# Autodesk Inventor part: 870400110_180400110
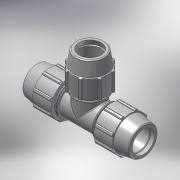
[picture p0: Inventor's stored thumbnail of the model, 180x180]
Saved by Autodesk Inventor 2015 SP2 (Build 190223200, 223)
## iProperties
Created: 2017-02
Part Number: 870400110_180400110
Material: PVC-Piping
Description: PLASSON TEE 110-110-110
Document SubType Name: Modeling
Designer: KIM
Mass: 92.6774 g
Surface Area: 199.44 cm^2
Volume: 66.1981 cm^3
Density: 1.4 g/cm^3
Appearance: Smooth - White
Author: KIM
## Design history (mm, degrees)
derived "87040.ipt"
feature "Solid1::87040.ipt"
tag "TaggingFeature1"
body "Solid1"
other parameters: "d4" = 24.5, "d5" = 73.5, "d7" = 181, "d13" = 120 deg, "d14" = 143, "d15" = 8 deg, "d18" = 5.5, "d19" = 35 deg, "d20" = 17.5 deg, "d21" = 168.33, "d23" = 0, "d25" = 360 deg, "d27" = 3.62, "d42" = 102.9, "d43" = 5.43, "d46" = 3.3, "d63" = 196, "d67" = 135.75, "d77" = 181, "d78" = 8 deg, "d79" = 294, "d80" = 120 deg, "d81" = 143, "d82" = 24.5, "d85" = 135.75, "d87" = 9.8, "d88" = 9.8, "d89" = 73.5, "d90" = 102.9, "d98" = 168.33, "d99" = 35 deg, "d100" = 17.5 deg, "d102" = 0, "d103" = 3.62, "d107" = 360 deg, "d109" = 3.3, "d112" = 5.5, "d118" = 360 deg, "d121" = 0, "d128" = 583, "d131" = 99, "d132" = 99, "d133" = 196, "d134" = 3.92, "d152" = 0, "d154" = 0, "d156" = 0, "d158" = 0, "d163" = 16.33333, "d165" = 19.6, "d166" = 128.9625, "d167" = 128.9625, "d168" = 3.92, "d169" = 149.325, "d170" = 1.96, "d171" = 6.86, "d172" = 142.5375, "d173" = 4.9, "d174" = 4.08333, "d175" = 3.675, "d176" = 2.2, "d177" = 5.5, "E_" = 181, "A_" = 294, "l_" = 196, "H_" = 583, "d162" = 19.6, "d164" = 23.52
